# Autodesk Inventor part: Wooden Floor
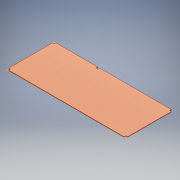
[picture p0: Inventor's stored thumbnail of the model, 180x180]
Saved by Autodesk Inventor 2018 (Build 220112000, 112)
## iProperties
Created: 2020-10
Part Number: Wooden Floor
Material: Wood (Oak)
Document SubType Name: Modeling
Designer: cadcr
Density: 0.76 g/cm^3
Appearance: White Oak - Natural Medium Gloss
Author: cadcr
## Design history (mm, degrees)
workplane "Work Plane1"
sketch "Sketch1"
  geometry: L1 (0, 1150)-(-38, 1150) reference; L2 (-38, 50)-(-38, 1150) reference; L3 (6, 1156)-(6, 1194) reference; L4 (6, 1194)-(2906, 1194) reference; L5 (2906, 1156)-(2906, 1194) reference; L6 (2912, 1150)-(2950, 1150) reference; L7 (2950, 1150)-(2950, 50) reference; L8 (2912, 50)-(2950, 50) reference; L9 (2906, 44)-(2906, 6) reference; L10 (6, 44)-(6, 6) reference; L11 (2906, 6)-(6, 6) reference; L12 (2906, 44)-(2906, 6) reference; L13 (2906, 44)-(6, 44) reference; L14 (0, 1150)-(-38, 1150) reference; L15 (-38, 50)-(-38, 1150) reference; L16 (0, 50)-(-38, 50) reference; L17 (0, 50)-(0, 1150) reference; L18 (0, 50)-(0, 1150) reference; L19 (0, 50)-(6, 50); L20 (6, 44)-(6, 50); L21 (0, 1150)-(6, 1150); L22 (6, 1156)-(6, 1150); L23 (2912, 1150)-(2906, 1150); L24 (2906, 1156)-(2906, 1150); L25 (2912, 50)-(2906, 50); L26 (2906, 44)-(2906, 50); L27 (1056, 1156)-(1056, 1194) reference; L28 (1106, 1194)-(1106, 1156) reference; L29 (1100, 1150)-(1062, 1150) reference; L30 (1106, 1156)-(1106, 1150); L31 (1100, 1150)-(1106, 1150); L32 (1056, 1156)-(1056, 1150); L33 (1062, 1150)-(1056, 1150); L34 (1056, 1194)-(6, 1194); L35 (1106, 1194)-(2906, 1194); 1 further point
  constraints: 28 end point, 7 perpendicular, 4 horizontal, 2 vertical, 1 point on line
extrude "Extrusion1" new body sketch "Sketch1" distance "d0" = 10; taper "d1" = 0 deg
body "Solid1"
node "Reference1"
node "Reference2"
node "Reference3"
node "Reference4"
node "Reference5"
node "Reference6"
node "Reference7"
node "Reference8"
node "Reference9"
node "Reference10"
node "Reference11"
node "Reference12"
node "Reference13"
node "Reference14"
node "Reference15"
node "Reference16"
